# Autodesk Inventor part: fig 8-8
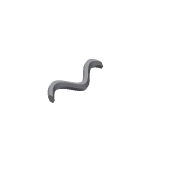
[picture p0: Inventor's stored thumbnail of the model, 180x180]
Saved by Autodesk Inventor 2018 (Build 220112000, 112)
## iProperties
Created: 2006-01
Part Number: fig 8-8
Document SubType Name: Modeling
Designer: CADCIM
Density: 1 g/cm^3
Material: Generic
Appearance: Default
Author: CADCIM
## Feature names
1. Sweep4
## Parameters: d3 = 0, d4 = 0
